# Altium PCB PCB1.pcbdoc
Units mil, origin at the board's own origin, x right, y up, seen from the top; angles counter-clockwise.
Board outline 10295 x 5570 mil, 2 copper layers (Top Layer, Bottom Layer); 41 components, 38 nets, 210 pads, 73 vias.
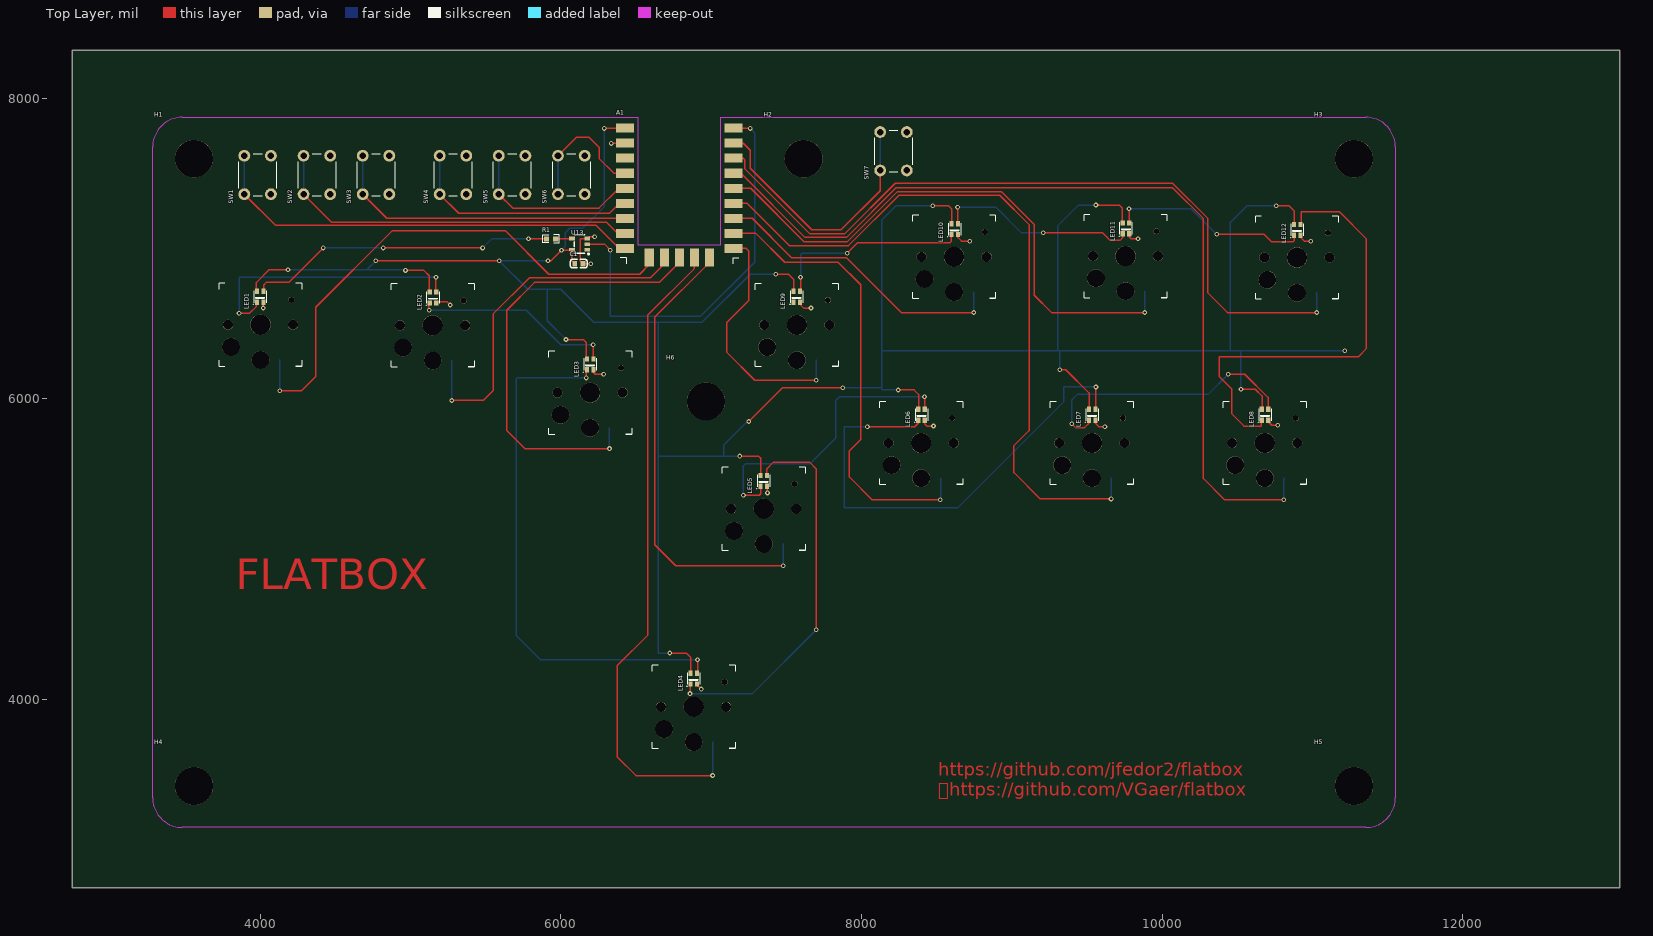
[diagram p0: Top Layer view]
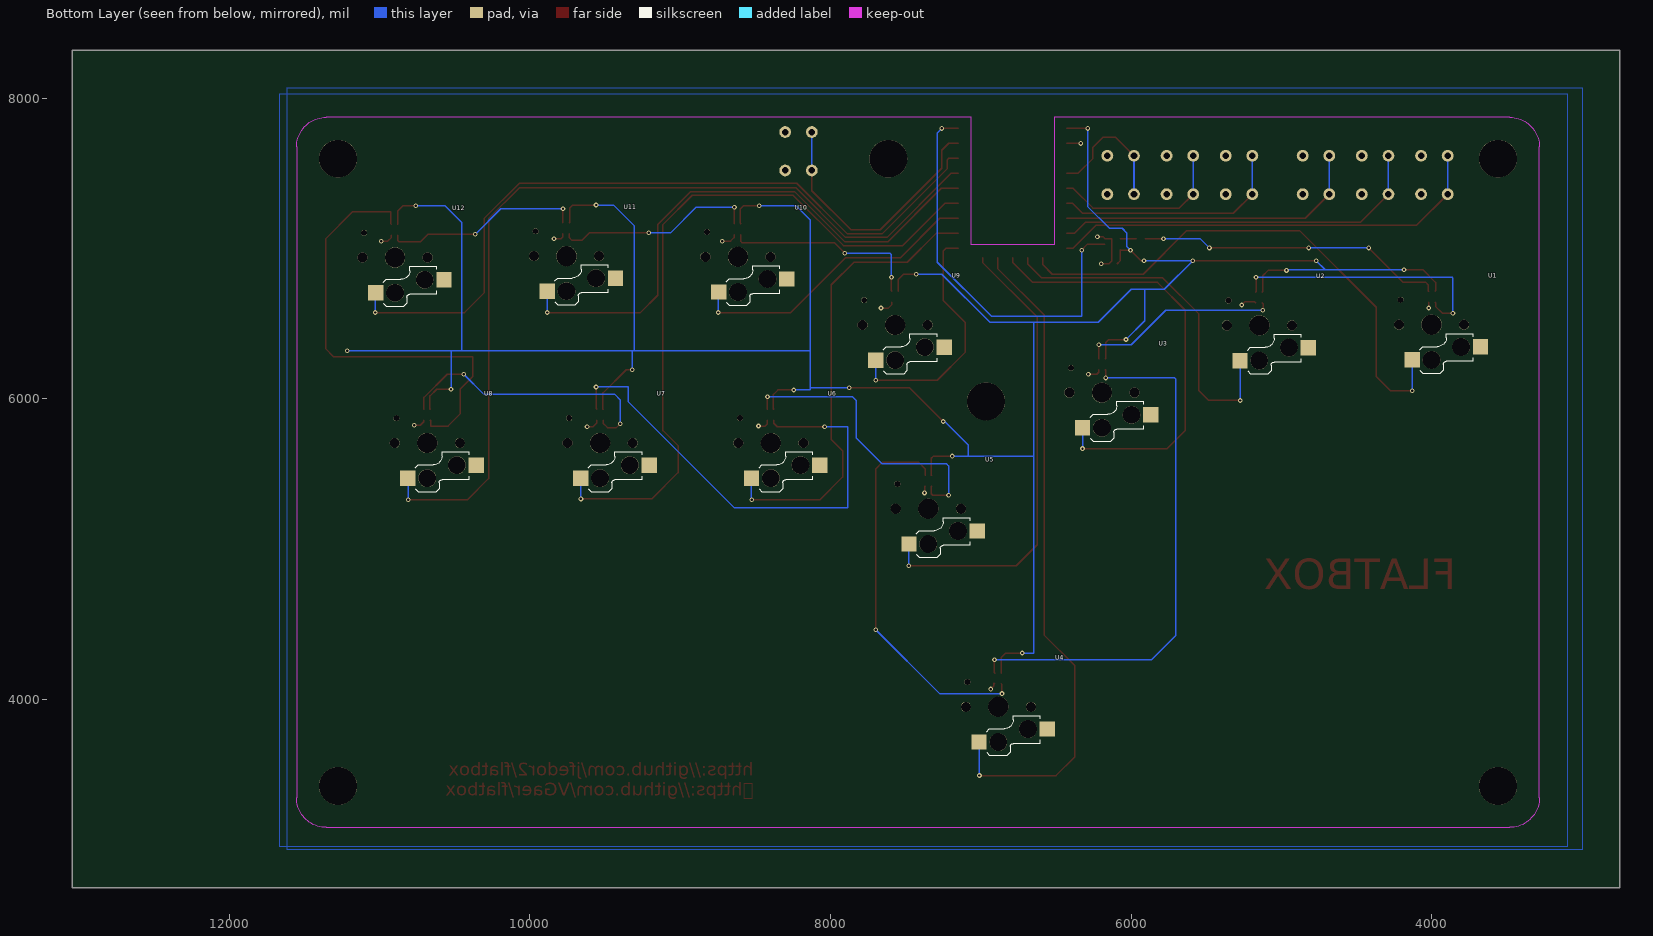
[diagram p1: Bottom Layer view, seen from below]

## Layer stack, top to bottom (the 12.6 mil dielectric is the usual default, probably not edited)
Top Layer: signal copper (thickness not stored)
Dielectric: dielectric 12.6, FR-4, Dk 4.8
Bottom Layer: signal copper (thickness not stored)

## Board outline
13045,2750 2750,2750 2750,8320 13045,8320

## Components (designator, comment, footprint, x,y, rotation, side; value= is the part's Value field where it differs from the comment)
A1 "RP2040-Zero_RP2040-Zero" RP2040-Zero:RP2040-Zero 6788.7,7401.5 r0 top
C1 "CAP_0603" C0603 6120,6900 r0 top
H1 "Mechanical_MountingHole" MountingHole:MountingHole_6.4mm_M6 3560.4,7598.3 r0 top
H2 "Mechanical_MountingHole" MountingHole:MountingHole_6.4mm_M6 7615.5,7598.3 r0 top
H3 "Mechanical_MountingHole" MountingHole:MountingHole_6.4mm_M6 11276.9,7598.3 r0 top
H4 "Mechanical_MountingHole" MountingHole:MountingHole_6.4mm_M6 3560.4,3425.1 r0 top
H5 "Mechanical_MountingHole" MountingHole:MountingHole_6.4mm_M6 11276.9,3425.1 r0 top
H6 "Mechanical_MountingHole" MountingHole:MountingHole_6.4mm_M6 6965.9,5984.1 r0 top
LED1 "WS2812B-2020" LED-SMD_4P-L2.0-W2.0-TL_WS2812B-2020 4000,6680 r90 top
LED2 "WS2812B-2020" LED-SMD_4P-L2.0-W2.0-TL_WS2812B-2020 5150,6675 r90 top
LED3 "WS2812B-2020" LED-SMD_4P-L2.0-W2.0-TL_WS2812B-2020 6195,6230 r90 top
LED4 "WS2812B-2020" LED-SMD_4P-L2.0-W2.0-TL_WS2812B-2020 6885,4140 r90 top
LED5 "WS2812B-2020" LED-SMD_4P-L2.0-W2.0-TL_WS2812B-2020 7350,5455 r90 top
LED6 "WS2812B-2020" LED-SMD_4P-L2.0-W2.0-TL_WS2812B-2020 8400,5895 r90 top
LED7 "WS2812B-2020" LED-SMD_4P-L2.0-W2.0-TL_WS2812B-2020 9535,5895 r90 top
LED8 "WS2812B-2020" LED-SMD_4P-L2.0-W2.0-TL_WS2812B-2020 10685,5895 r90 top
LED9 "WS2812B-2020" LED-SMD_4P-L2.0-W2.0-TL_WS2812B-2020 7570,6680 r90 top
LED10 "WS2812B-2020" LED-SMD_4P-L2.0-W2.0-TL_WS2812B-2020 8620,7130 r90 top
LED11 "WS2812B-2020" LED-SMD_4P-L2.0-W2.0-TL_WS2812B-2020 9760,7135 r90 top
LED12 "WS2812B-2020" LED-SMD_4P-L2.0-W2.0-TL_WS2812B-2020 10900,7125 r90 top
R1 "Res_0603" R0603 5935.34,7065 r0 top
SW1 "TS-1002-AR05026" Button_Switch_THT:SW_PUSH_6mm_H5mm 3895,7362.1 r90 top
SW2 "TS-1002-AR05026" Button_Switch_THT:SW_PUSH_6mm_H5mm 4288.7,7362.1 r90 top
SW3 "TS-1002-AR05026" Button_Switch_THT:SW_PUSH_6mm_H5mm 4682.4,7362.1 r90 top
SW4 "TS-1002-AR05026" Button_Switch_THT:SW_PUSH_6mm_H5mm 5194.2,7362.1 r90 top
SW5 "TS-1002-AR05026" Button_Switch_THT:SW_PUSH_6mm_H5mm 5587.9,7362.1 r90 top
SW6 "TS-1002-AR05026" Button_Switch_THT:SW_PUSH_6mm_H5mm 5981.6,7362.1 r90 top
SW7 "TS-1002-AR05026" Button_Switch_THT:SW_PUSH_6mm_H5mm 8125,7520 r90 top
U1 "CPG135001D02" Kailh_socket_PG1350 4002.3,6494 r0 top
U2 "CPG135001D02" Kailh_socket_PG1350 5147.8,6489.3 r0 top
U3 "CPG135001D02" Kailh_socket_PG1350 6195,6042.4 r0 top
U4 "CPG135001D02" Kailh_socket_PG1350 6884,3951.9 r0 top
U5 "CPG135001D02" Kailh_socket_PG1350 7349.8,5269.6 r0 top
U6 "CPG135001D02" Kailh_socket_PG1350 8397.4,5707 r0 top
U7 "CPG135001D02" Kailh_socket_PG1350 9533.2,5707 r0 top
U8 "CPG135001D02" Kailh_socket_PG1350 10683.2,5707 r0 top
U9 "CPG135001D02" Kailh_socket_PG1350 7570.6,6491.6 r0 top
U10 "CPG135001D02" Kailh_socket_PG1350 8616.3,6945.6 r0 top
U11 "CPG135001D02" Kailh_socket_PG1350 9756.8,6950.3 r0 top
U12 "CPG135001D02" Kailh_socket_PG1350 10897.4,6940.8 r0 top
U13 "SN74LV1T34DBVR" SOT-23-5_L3.0-W1.7-P0.95-LS2.8-BR 6125,7030 r0 top

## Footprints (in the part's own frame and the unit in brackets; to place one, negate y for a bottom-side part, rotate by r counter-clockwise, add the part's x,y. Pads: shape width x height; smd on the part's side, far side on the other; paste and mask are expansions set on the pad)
Button_Switch_THT:SW_PUSH_6mm_H5mm [mm]
  round 2 hole 1.1: 1(0,0) 2(6.5,-4.5) 3(6.5,0) 4(0,-4.5)
  silkscreen extent -0.25,-5.5 6.75,1
C0603 [mm]
  rect 0.8x0.9 smd: 1(-0.7,0) 2(0.7,0)
  silkscreen extent -1.41,-0.71 1.39,0.72
Kailh_socket_PG1350 [mm]
  rect 2.6x2.6 smd far side: 1(3.275,-5.95) 2(-8.275,-3.75)
  round 0.991 hole 0.991 unplated: 3(5.22,4.2)
  round 3 hole 3 unplated: 4(0,-5.95) 6(-5,-3.75)
  round 3.429 hole 3.429 unplated: 5(0,0)
  round 1.702 hole 1.702 unplated: 7(5.5,0) 8(-5.5,0)
  silkscreen extent -7,-7 7,7
LED-SMD_4P-L2.0-W2.0-TL_WS2812B-2020 [mm]
  rect 0.9x0.7 smd: 1(-0.915,0.55) 2(-0.915,-0.55) 3(0.915,-0.55) 4(0.915,0.55)
  silkscreen extent -1.3,-1.1 1,1.15
MountingHole:MountingHole_6.4mm_M6 [mm]
  round 6.4 hole 6.4 unplated: 1(0,0)
R0603 [mil]
  rect 31.75x34.02 smd: 1(-29.66,0) 2(29.66,0)
  silkscreen extent -55,-26 55,26
RP2040-Zero:RP2040-Zero [mm]
  rect 3x1.524 smd: 1(9.16,10.16) 2(9.16,7.62) 3(9.16,5.08) 4(9.16,2.54) 5(9.16,0) 6(9.16,-2.54) 7(9.16,-5.08) 8(9.16,-7.62) 9(9.16,-10.16) 15(-9.16,-10.16) 16(-9.16,-7.62) 17(-9.16,-5.08) 18(-9.16,-2.54) 19(-9.16,0) 20(-9.16,2.54) 21(-9.16,5.08) 22(-9.16,10.16) 23(-9.16,7.62)
  rect 1.524x3 smd: 10(5.08,-11.7) 11(2.54,-11.7) 12(0,-11.7) 13(-2.54,-11.7) 14(-5.08,-11.7)
  silkscreen extent -10,-12.75 10,-11.75
SOT-23-5_L3.0-W1.7-P0.95-LS2.8-BR [mm]
  rect 1x0.6 smd: 1(1.3,-0.95) 2(1.3,0) 3(1.3,0.95) 4(-1.3,0.95) 5(-1.3,-0.95)
  silkscreen extent -0.9,-1.78 1.65,1.55

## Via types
v1: diameter 31.5, hole 15.7, Top Layer to Bottom Layer, 73 vias

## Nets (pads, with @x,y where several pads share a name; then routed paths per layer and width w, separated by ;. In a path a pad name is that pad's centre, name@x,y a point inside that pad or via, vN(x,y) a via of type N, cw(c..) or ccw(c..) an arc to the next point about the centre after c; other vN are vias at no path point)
1K: A1.10 U5.1 | length 3120.4
  Top Layer w10: A1.10 6988.7,6908.7 6625,6545 6625,5030 6765,4890 v1(7480,4890)
  Bottom Layer w10: U5.1 7480,5034.09 v1(7480,4890)
1P: A1.9 U9.1 | length 1646.7
  Top Layer w10: A1.9 7233.5,7001.5 7250,6985 7250,6655 7105,6510 7105,6310 7290,6125 v1(7700,6125)
  Bottom Layer w10: U9.1 7700,6256.89 v1(7700,6125)
2K: A1.8 U6.1 | length 3108.6
  Top Layer w10: A1.8 7298.5,7101.5 7490,6910 7845,6910 7995,6760 7995,5730 7920,5655 7920,5480 8070,5330 v1(8525,5330)
  Bottom Layer w10: v1(8525,5330) 8526.34,5331.34 U6.1
2P: A1.7 U10.1 | length 1995
  Top Layer w10: A1.7 7273.5,7201.5 7535,6940 7900,6940 8265,6575 v1(8747.56,6575)
  Bottom Layer w10: U10.1 8747.56,6709.03 v1(8747.56,6575)
3K: A1.6 U7.1 | length 4849.9
  Top Layer w10: A1.6 7238.5,7301.5 7520,7020 7915,7020 8250,7355 8920,7355 9115,7160 9115,5790 9015,5690 9015,5510 9190,5335 v1(9660.99,5335)
  Bottom Layer w10: v1(9660.99,5335) 9660.99,5471.6 U7.1
3P: A1.5 U11.1 | length 3772.2
  Top Layer w10: A1.5 7263.5,7401.5 7620,7045 7905,7045 8240,7380 8930,7380 9150,7160 9150,6690 9265,6575 v1(9885,6575)
  Bottom Layer w10: v1(9885,6575) 9885,6715.31 U11.1
4K: A1.4 U8.1 | length 5990.6
  Top Layer w10: A1.4 7198.5,7501.5 7625,7075 7900,7075 8230,7405 10070,7405 10275,7200 10275,5470 10415,5330 v1(10810,5330)
  Bottom Layer w10: v1(10810,5330) 10810,5470.61 U8.1
4P: A1.3 U12.1 | length 5041.6
  Top Layer w10: A1.3 7213.5,7601.5 7225,7590 7225,7530 7655,7100 7890,7100 8225,7435 10070,7435 10305,7200 10305,6705 10435,6575 v1(11030,6575)
  Bottom Layer w10: U12.1 11030,6702.89 v1(11030,6575)
$2N23874: U13.4
+5V: C1.1 LED1.4 LED2.4 LED3.4 LED4.4 LED5.4 LED6.4 LED7.4 LED8.4 LED9.4 LED10.4 LED11.4 LED12.4 U13.5 | length 20655.9
  Top Layer w10: LED1.4 3975,6719.37 3975,6775 4060,6860 v1(4185,6860) ; v1(4769.97,6920) v1(5590,6920) ; v1(4967.49,6855.11) 5089.89,6855.11 5125,6820 5125,6714.37 LED2.4 ; v1(5915,6920) 5935,6920 v1(6005,6990) 6071.22,6990 U13.5 ; v1(6035.27,6395.22) 6149.78,6395.22 6170,6375 6170,6269.37 LED3.4 ; U13.5@6074.06,6992.64 6074.06,6918.39 C1.1 ; v1(6290,7800) 6291.5,7801.5 6428.07,7801.5 ; v1(6725,4310) 6835,4310 6865,4280 6865,4177.68 LED4.4 ; v1(7190,5620) 7315,5620 7330,5605 7330,5492.68 LED5.4 ; v1(7250,5850) 7475,6075 v1(7875,6075) ; v1(7430,6830) 7515,6830 7550,6795 7550,6717.68 LED9.4 ; v1(8245,6060) 8350,6060 8380,6030 8380,5932.68 LED6.4 ; v1(8475,7285) 8580,7285 8600,7265 8600,7167.68 LED10.4 ; v1(9320,6195) 9360,6195 9515,6040 9515,5932.68 LED7.4 ; v1(9560,7290) 9715,7290 9735,7270 9735,7174.37 LED11.4 ; v1(10525,6065) 10620,6065 10665,6020 10665,5932.68 LED8.4 ; v1(10760,7285) 10845,7285 10880,7250 10880,7162.68 LED12.4
  Bottom Layer w10: v1(4185,6860) 4709.97,6860 ; v1(4769.97,6920) 4709.97,6860 ; v1(4967.49,6855.11) 4962.6,6860 4709.97,6860 ; v1(5915,6920) v1(5590,6920) 5780,6730 5909.62,6730 ; v1(6005,6990) 6030,7015 6030,7105 6060,7135 6145,7135 6290,7280 v1(6290,7800) ; v1(6035.27,6395.22) 5909.62,6520.87 5909.62,6730 ; v1(6725,4310) 6650,4310 6650,5620.22 ; v1(7190,5620) 7083.68,5620 ; v1(7250,5850) 7240,5850 7083.68,5693.68 7083.68,5620 ; v1(7430,6830) 7260,6830 6940,6510 6650,6510 ; v1(7875,6075) 8133.82,6075 8136,6077.18 ; v1(8245,6060) 8136,6060 8136,6077.18 ; v1(8475,7285) 8230,7285 8136,7191 8136,6321.35 ; v1(9320,6195) 9320,6321.35 ; v1(9560,7290) 9445,7290 9305,7150 9305,6321.5 9305.16,6321.35 ; v1(10525,6065) 10525,6317.7 10521.35,6321.35 ; v1(10760,7285) 10565,7285 10455,7175 10455,6322.61 10456.26,6321.35 ; v1(11215,6320) 11213.65,6321.35 10521.35,6321.35 ; 5909.62,6730 6000,6730 6220,6510 6650,6510 ; 6650,5620.22 6650.22,5620 7083.68,5620 ; 6650,5620.22 6650,6510 ; 8136,6077.18 8136,6321.35 ; 8136,6321.35 9305.16,6321.35 ; 9305.16,6321.35 9320,6321.35 ; 9320,6321.35 10456.26,6321.35 ; 10456.26,6321.35 10521.35,6321.35
DOWN: A1.13 U2.1 | length 2396.8
  Top Layer w10: v1(5275,5990) 5485,5990 5550,6055 5550,6565 5790,6805 6595,6805 6688.7,6898.7 A1.13
  Bottom Layer w10: v1(5275,5990) 5275,6253.31 U2.1
GND: A1.23 C1.2 LED1.2 LED2.2 LED3.2 LED4.2 LED5.2 LED6.2 LED7.2 LED8.2 LED9.2 LED10.2 LED11.2 LED12.2 SW1.2 SW2.2 SW3.2 SW4.2 SW5.2 SW6.2 SW7.2 U1.2 U2.2 U3.2 U4.2 U5.2 U6.2 U7.2 U8.2 U9.2 U10.2 U11.2 U12.2 U13.3 | length 1408.7
  Top Layer w10: v1(4020,6605) 4021.66,6606.65 LED1.2 ; LED2.2 5178.15,6645.47 5244.53,6645.47 v1(5265,6625) ; v1(6200,6900) C1.2 6130,6917.56 6130,7065 6132.44,7067.44 6175.94,7067.44 6188.51,7080 v1(6225,7080) ; LED3.2 6216.65,6178.35 6230,6165 v1(6285,6165) ; v1(6335,7700) 6426.57,7700 A1.23 ; LED4.2 6913.15,4110.47 6913.15,4091.85 v1(6935,4070) ; LED5.2 7375,5415.63 v1(7375,5375) ; LED9.2 7591.65,6628.35 7615,6605 v1(7665,6605) ; LED6.2 8421.66,5833.35 8435,5820 v1(8480,5820) ; LED10.2 8641.66,7073.35 8665,7050 v1(8720,7050) ; LED7.2 9556.66,5838.35 9580,5815 v1(9620,5815) ; LED11.2 9781.66,7078.35 9795,7065 v1(9840,7065) ; LED8.2 10706.66,5848.35 10730,5825 v1(10770,5825) ; LED12.2 10921.66,7074.83 10946.49,7050 v1(10990,7050)
LEFT: A1.14 U1.1 | length 3568.2
  Top Layer w10: v1(4130,6055) 4275,6055 4370,6150 4370,6610 4880,7120 5630,7120 5920,6830 6525,6830 6588.7,6893.7 A1.14
  Bottom Layer w10: v1(4130,6055) 4130,6258.51 U1.1
OPT1: A1.15 SW1.1 | length 2938.3
  Top Layer w10: SW1.1 4102.1,7155 6235,7155 6388.5,7001.5 A1.15
  Bottom Layer w10: SW1.1 3895,7618.01
OPT2: A1.16 SW2.1 | length 2503.2
  Top Layer w10: SW2.1 4475.8,7175 6305,7175 6378.5,7101.5 A1.16
  Bottom Layer w10: SW2.1 4288.7,7618.01
OPT3: A1.17 SW3.1 | length 2068.1
  Top Layer w10: SW3.1 4843,7201.5 A1.17
  Bottom Layer w10: SW3.1 4682.4,7618.01
OPT4: A1.18 SW4.1 | length 1570
  Top Layer w10: SW4.1 5321.3,7235 6325,7235 6391.5,7301.5 A1.18
  Bottom Layer w10: SW4.1 5194.2,7618.01
OPT5: A1.19 SW5.1 | length 1188.7
  Top Layer w10: SW5.1 5680,7270 6255,7270 6386.5,7401.5 A1.19
  Bottom Layer w10: SW5.1 5587.9,7618.01
OPT6: A1.20 SW6.1 SW6.3 | length 895.6
  Top Layer w10: SW6.3 6103.6,7740 6190,7740 6255,7675 6255,7600 6353.5,7501.5 A1.20
  Bottom Layer w10: SW6.1 SW6.3
OPT7: A1.2 SW7.1 | length 1783.3
  Top Layer w10: A1.2 7213.38,7701.5 7260,7654.88 7260,7535 7670,7125 7865,7125 8125,7385 SW7.1
  Bottom Layer w10: SW7.1 8125,7775.9
RGB: R1.2 | length 110.1
  Top Layer w10: R1.2 5967.44,7067.44 6074.06,7067.44
RGB0: LED1.3 R1.1 | length 2052.4
  Top Layer w10: LED1.3 4025,6719.37 4025,6760 4040,6775 4190,6775 v1(4420,7005) ; v1(4819.53,7005) v1(5480,7005) ; v1(5785,7065) R1.1
  Bottom Layer w10: v1(4420,7005) v1(4819.53,7005) ; v1(5480,7005) 5540,7065 v1(5785,7065)
RGB1: LED1.1 LED2.3 | length 1810.7
  Top Layer w10: v1(3860,6570) 3930,6570 3975,6615 3975,6640.63 LED1.1 ; v1(5170,6810) 5170,6712.68 LED2.3
  Bottom Layer w10: v1(3860,6570) 3860,6805 3865,6810 v1(5170,6810)
RGB2: LED2.1 LED3.3 | length 1332.9
  Top Layer w10: v1(5125,6590) 5121.85,6593.15 5121.85,6632.48 LED2.1 ; v1(6215,6360) 6215,6267.68 LED3.3
  Bottom Layer w10: v1(5125,6590) 5770,6590 6000,6360 v1(6215,6360)
RGB3: LED3.1 LED4.3 | length 3594.3
  Top Layer w10: v1(6170,6140) 6170,6190.63 LED3.1 ; LED4.3 6906.34,4176.34 6910,4180 v1(6910,4265)
  Bottom Layer w10: v1(6170,6140) 5710,6140 5705,6135 5705,4425 5865,4265 v1(6910,4265)
RGB4: LED4.1 LED5.3 | length 2563.3
  Top Layer w10: v1(6860,4040) 6860,4100.63 LED4.1 ; LED5.3 7370,5492.68 7370,5535 7415,5580 7655,5580 7700,5535 v1(7700,4465)
  Bottom Layer w10: v1(6860,4040) 7275,4040 v1(7700,4465)
RGB5: LED5.1 LED6.3 | length 1990.4
  Top Layer w10: v1(7215,5360) 7320,5360 7330,5370 7330,5417.32 LED5.1 ; v1(8420,6015) 8420,5932.68 LED6.3
  Bottom Layer w10: v1(7215,5360) 7215,5555 7230,5570 7660,5570 7830,5740 7830,5990 7855,6015 v1(8420,6015)
RGB6: LED6.1 LED7.3 | length 3282.4
  Top Layer w10: v1(8040,5815) 8355,5815 8378.34,5838.35 LED6.1 ; LED7.3 9555,5932.68 9560,5937.68 v1(9560,6080)
  Bottom Layer w10: v1(8040,5815) 7885,5815 7885,5275 8640,5275 9345,5980 9345,6080 v1(9560,6080)
RGB7: LED7.1 LED8.3 | length 1835.4
  Top Layer w10: v1(9400,5835) 9425,5810 9485,5810 9513.34,5838.35 LED7.1 ; v1(10440,6165) 10550,6165 10705,6010 10705,5932.68 LED8.3
  Bottom Layer w10: v1(9400,5835) 9400,5995 9435,6030 10305,6030 v1(10440,6165)
RGB8: LED8.1 LED12.3 | length 3011.4
  Top Layer w10: LED8.1 10660,5855.63 10660,5820 10545,5820 10465,5900 10465,6065 10380,6150 10380,6280 11305,6280 11360,6335 11360,7065 11180,7245 10925,7245 10925,7164.37 LED12.3
RGB9: LED11.3 LED12.1 | length 1322.5
  Top Layer w10: v1(9780,7265) 9781.66,7263.35 LED11.3 ; v1@10365,7095 10680,7095 10730,7045 10870,7045 10878.34,7053.35 LED12.1
  Bottom Layer w10: v1(9780,7265) 10194.33,7265 v1(10364.33,7095)
RGB10: LED10.3 LED11.1 | length 1332.4
  Top Layer w10: v1(8640,7275) 8641.66,7273.35 LED10.3 ; v1(9210,7105) 9605,7105 9655,7055 9720,7055 9738.34,7073.35 LED11.1
  Bottom Layer w10: v1(8640,7275) 8895,7275 9065,7105 v1(9210,7105)
RGB11: LED9.3 LED10.1 | length 1330.9
  Top Layer w10: LED9.3 7595,6719.37 v1(7595,6810) ; v1(7905,6970) 7975,7040 8590,7040 8598.34,7048.35 LED10.1
  Bottom Layer w10: v1(7595,6810) 7595,6960 7605,6970 v1(7905,6970)
RGBDATA: A1.1 U13.2 | length 2733.4
  Top Layer w10: U13.2@6175.94,7029.96 6290.04,7029.96 v1(6330,6990) ; A1.1 7258.5,7801.5 v1(7260,7800)
  Bottom Layer w10: v1(6330,6990) 6330,6550 6930,6550 7290,6910 7290,7770 v1(7260,7800)
RGBOUT: LED9.1
RIGHT: A1.12 U3.1 | length 2984.7
  Top Layer w10: v1(6323.94,5670) 5760,5670 5640,5790 5640,6590 5825,6775 6655,6775 6788.7,6908.7 A1.12
  Bottom Layer w10: v1(6323.94,5670) U3.1
UP: A1.11 U4.1 | length 4444.3
  Top Layer w10: A1.11 6888.7,6868.7 6580,6560 6580,4430 6375,4225 6375,3620 6500,3495 v1(7010,3495)
  Bottom Layer w10: v1(7010,3495) 7010,3714.71 U4.1
"": A1.21 A1.22 H1.1 H2.1 H3.1 H4.1 H5.1 H6.1 SW1.3 SW1.4 SW2.3 SW2.4 SW3.3 SW3.4 SW4.3 SW4.4 SW5.3 SW5.4 SW6.4 SW7.3 SW7.4 U1.3 U1.4 U1.5 U1.6 U1.7 U1.8 U2.3 U2.4 U2.5 U2.6 U2.7 U2.8 U3.3 U3.4 U3.5 U3.6 U3.7 U3.8 U4.3 U4.4 U4.5 U4.6 U4.7 U4.8 U5.3 U5.4 U5.5 U5.6 U5.7 U5.8 U6.3 U6.4 U6.5 U6.6 U6.7 U6.8 U7.3 U7.4 U7.5 U7.6 U7.7 U7.8 U8.3 U8.4 U8.5 U8.6 U8.7 U8.8 U9.3 U9.4 U9.5 U9.6 U9.7 U9.8 U10.3 U10.4 U10.5 U10.6 U10.7 U10.8 U11.3 U11.4 U11.5 U11.6 U11.7 U11.8 U12.3 U12.4 U12.5 U12.6 U12.7 U12.8 U13.1

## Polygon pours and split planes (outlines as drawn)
GND on Bottom Layer (solid, remove dead copper, pour order 0): 3000,3000 11615,3000 11615,8070 3000,8070
GND on Bottom Layer (solid, remove dead copper, pour order 1): 3100,3020 11665,3020 11665,8030 3100,8030

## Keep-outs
Board Outline Layer:
  lines w5.9 net "": 11355.6,7873.9 7064.3,7873.9 7064.3,7027.4 6513.1,7027.4 6513.1,7873.9 3481.7,7873.9 ccw(c3481.7,7677) 3284.8,7677 3284.8,3346.4 ccw(c3481.7,3346.4) 3481.7,3149.5 11355.7,3149.5 ccw(c11355.65,3346.35) 11552.5,3346.4 11552.5,7677 ccw(c11355.65,7677.05) 11355.7,7873.9

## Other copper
Top Layer:
  text "FLATBOX" at 3836.63,4734.93 h204.44
  text "https://github.com/jfedor2/flatbox /  https://github.com/VGaer/flatbox" at 8511.77,3361.64 h86.82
